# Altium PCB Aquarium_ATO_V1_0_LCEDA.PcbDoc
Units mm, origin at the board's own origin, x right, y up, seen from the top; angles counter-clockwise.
Board outline 120 x 72 mm, 2 copper layers (Top Layer, Bottom Layer), stack 1.58 mm thick; 64 components, 41 nets, 182 pads, 109 vias.
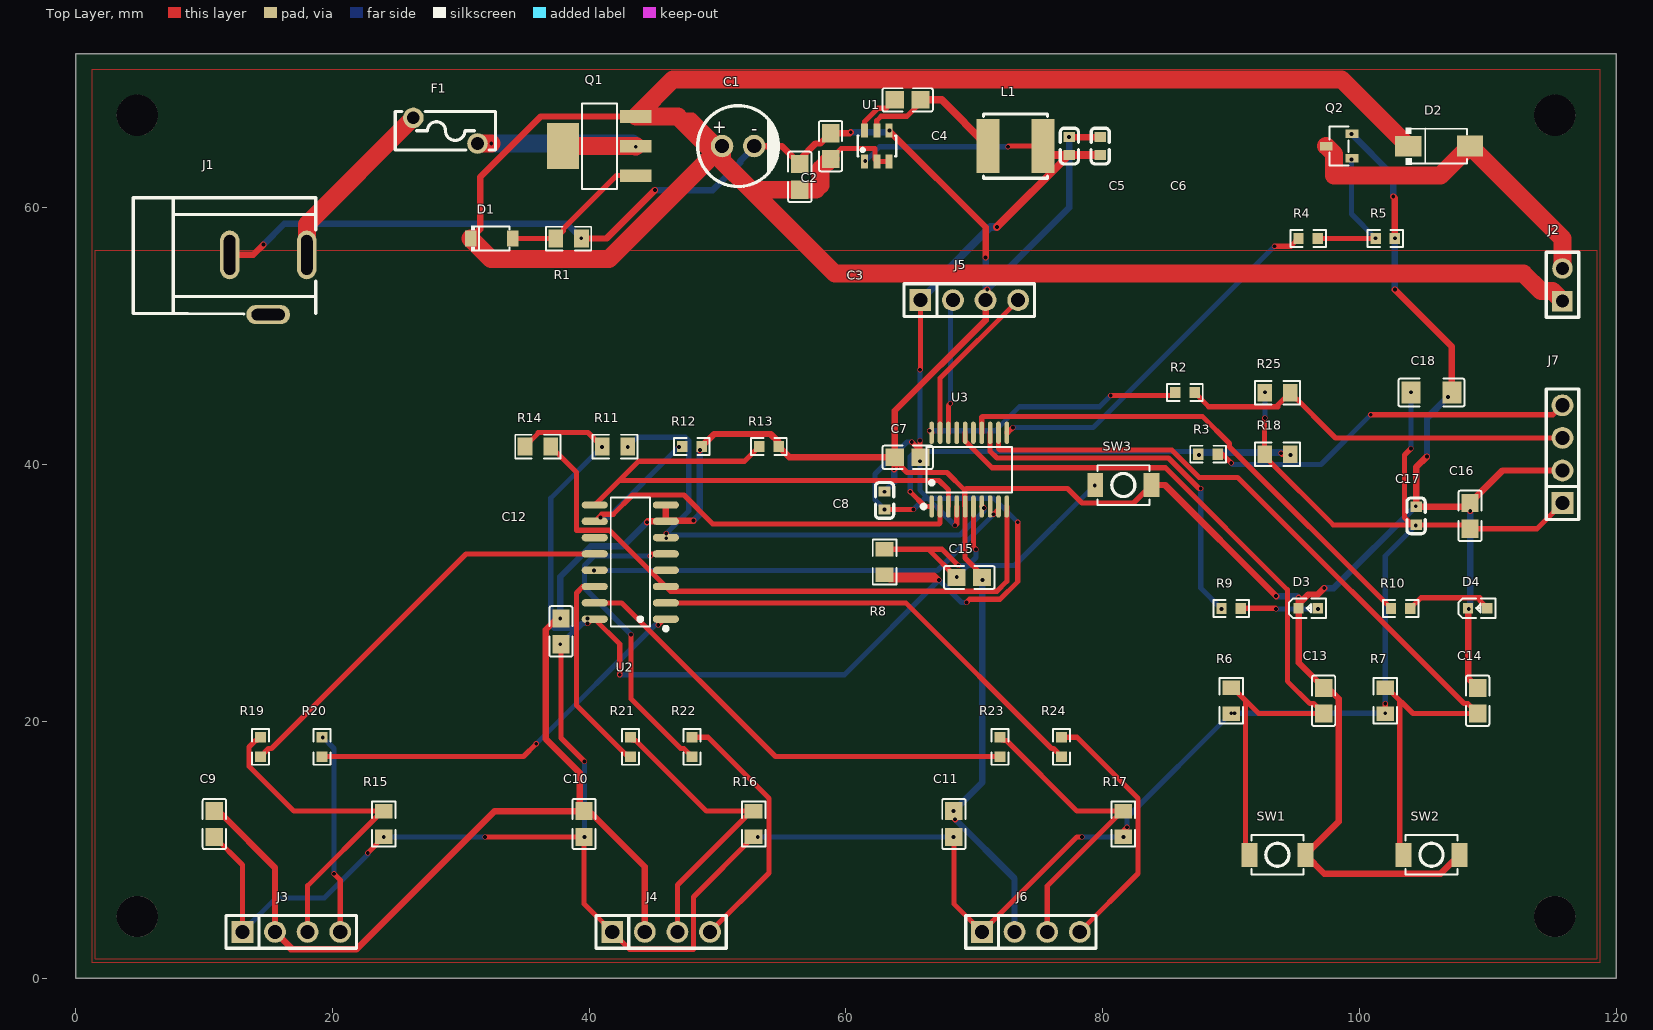
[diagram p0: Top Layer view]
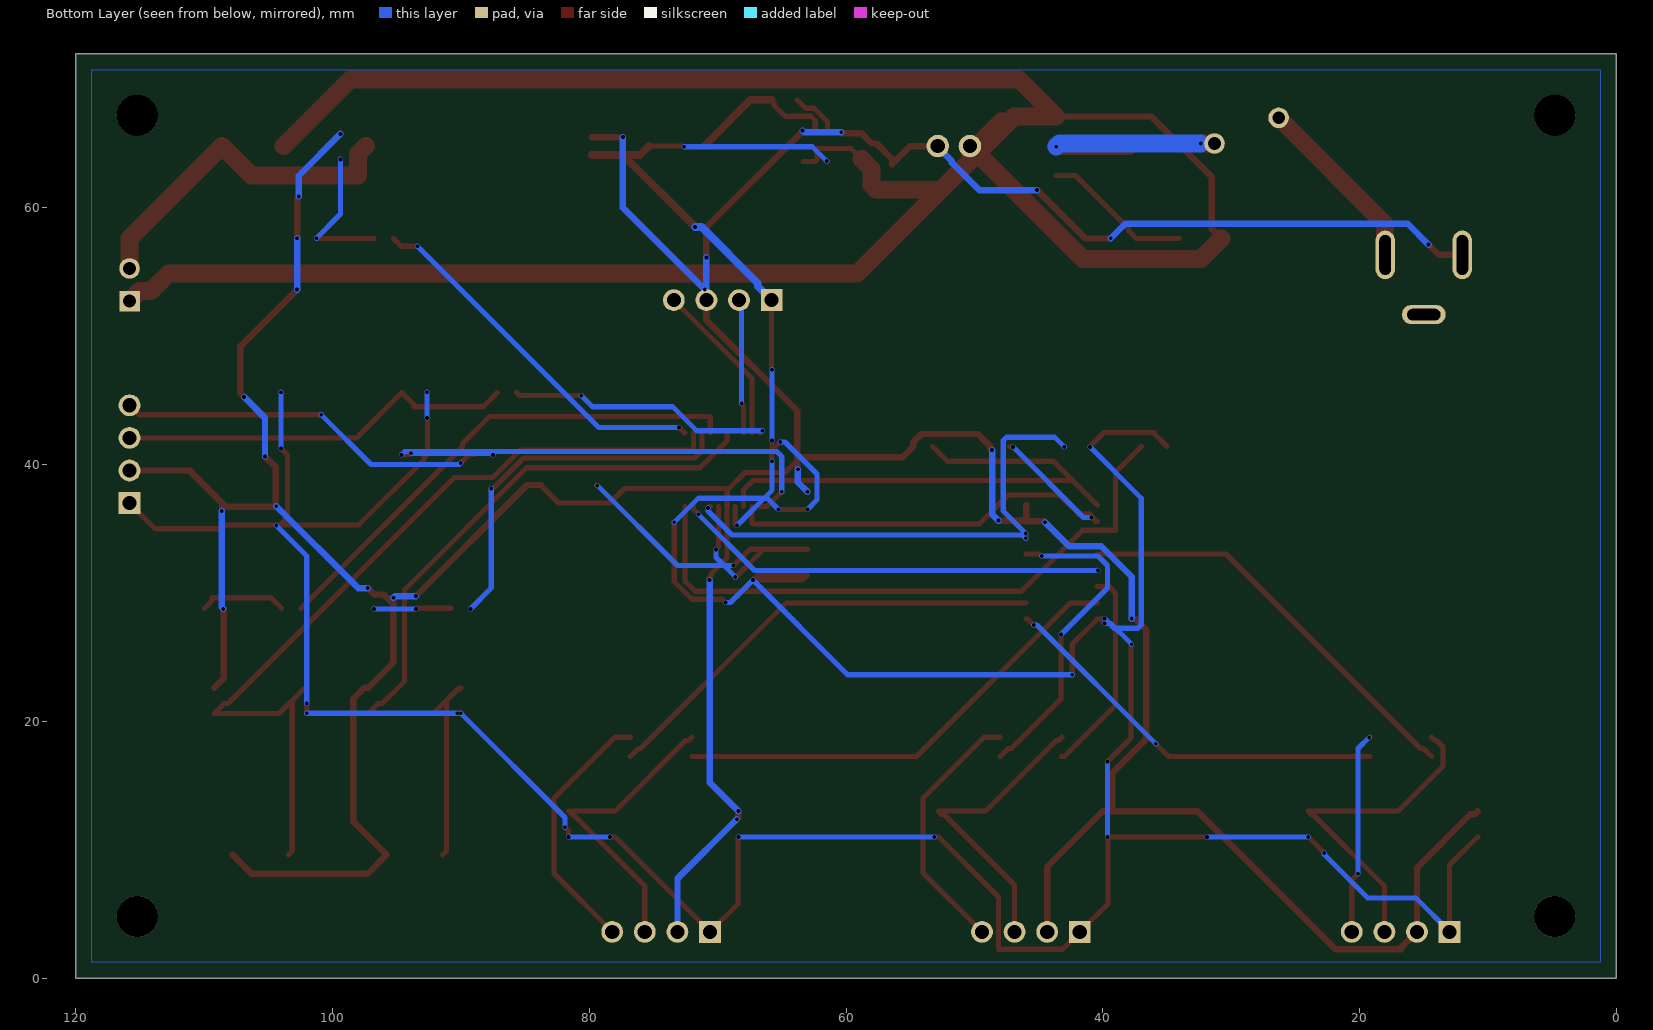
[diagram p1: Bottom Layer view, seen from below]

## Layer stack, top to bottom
Top Solder Mask Layer: solder mask 0.0102, Dk 3.3
Top Layer: signal copper 0.0356
Dielectric1: surface 1.5088, FR4, Dk 4.5
Bottom Layer: signal copper 0.0356
Bottom Solder Mask Layer: solder mask 0.0102, Dk 3.3

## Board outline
0,0 120,0 120,72 0,72

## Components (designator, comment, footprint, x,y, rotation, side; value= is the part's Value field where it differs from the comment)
C1 "47uF" CAP-TH_BD6.3-P2.50-D0.6-FD 51.6,64.8 r0 top
C2 "10uF" C0805#1 56.4,62.4 r90 top
C3 "100nF" C0805#1 58.8,64.8 r90 top
C4 "100nF" C0805#2 64.8,68.4 r0 top
C5 "22uF" C0603#1 77.4,64.8 r90 top
C6 "22uF" C0603#1 79.8,64.8 r90 top
C7 "100nF" C0805#2 64.8,40.56 r180 top
C8 "4.7uF" C0603#2 63,37.2 r90 top
C9 "100nF" C0805#2 10.8,12 r90 top
C10 "100nF" C0805#3 39.6,12 r90 top
C11 "100nF" C0805#2 68.4,12 r90 top
C12 "100nF" C0805#2 37.8,27 r90 top
C13 "100nF" C0805#2 97.2,21.6 r90 top
C14 "100nF" C0805#2 109.2,21.6 r90 top
C15 "100nF" C0805#3 69.6,31.2 r0 top
C16 "100nF" C0805#2 108.6,36 r90 top
C17 "10uF" C0603#2 104.4,36 r90 top
C18 "220uF" C1206 105.6,45.6 r0 top
D1 "BZT52C10" SOD-123_L2.7-W1.6-LS3.7-RD 32.4,57.6 r0 top
D2 "SS16" SMA_L4.3-W2.6-LS5.0-RD 106.2,64.8 r0 top
D3 "FC-1608G1-520" LED0603-RD 96,28.8 r0 top
D4 "XL-1608SURC-06" LED0603-RD_RED 109.2,28.8 r0 top
F1 "RL60-050" FUSE-TH_L7.8-W3.0-P5.10-D0.5-S2.00 28.8,66 r0 top
J1 "DC005-T25" DC-IN-TH_DC-005-20A-1 15,54 r0 top
J2 "LAIL-PZ2.54-2P-L" CONN-TH_LAIL-PZ2.54-2P-L 115.8,54 r90 top
J3 "HX PZ2.54-1x4P ZZ" HDR-TH_4P-P2.54-V-M 16.8,3.6 r0 top
J4 "HX PZ2.54-1x4P ZZ" HDR-TH_4P-P2.54-V-M 45.6,3.6 r0 top
J5 "HX PZ2.54-1x4P ZZ" HDR-TH_4P-P2.54-V-M 69.6,52.8 r0 top
J6 "HX PZ2.54-1x4P ZZ" HDR-TH_4P-P2.54-V-M 74.4,3.6 r0 top
J7 "HX PZ2.54-1x4P ZZ" HDR-TH_4P-P2.54-V-M 115.8,40.8 r90 top
L1 "3.9uH" IND-SMD_L5.0-W5.0_FNR50XXS 73.2,64.8 r0 top
Q1 "DMP6023LE-13" SOT-223-4_L6.5-W3.5-P2.30-LS7.0-BR 40.8,64.8 r0 top
Q2 "AO3400A" SOT-23-3_L2.9-W1.3-P1.90-LS2.4-BR 98.4,64.8 r0 top
R1 "47kΩ" R0805 38.4,57.6 r0 top
R2 "1kΩ" R0603#1 86.4,45.6 r0 top
R3 "1kΩ" R0603#2 88.2,40.8 r0 top
R4 "1kΩ" R0603#1 96,57.6 r0 top
R5 "100kΩ" R0603#2 102,57.6 r0 top
R6 "10kΩ" R0805 90,21.6 r90 top
R7 "10kΩ" R0805 102,21.6 r90 top
R8 "10kΩ" R0805 63,32.4 r90 top
R9 "1kΩ" R0603#2 90,28.8 r0 top
R10 "1kΩ" R0603#1 103.2,28.8 r0 top
R11 "10kΩ" R0805 42,41.4 r0 top
R12 "100kΩ" R0603#2 48,41.4 r0 top
R13 "100kΩ" R0603#1 54,41.4 r0 top
R14 "10kΩ" R0805 36,41.4 r0 top
R15 "10kΩ" R0805 24,12 r90 top
R16 "10kΩ" R0805 52.8,12 r90 top
R17 "10kΩ" R0805 81.6,12 r90 top
R18 "10kΩ" R0805 93.6,40.8 r0 top
R19 "1kΩ" R0603#1 14.4,18 r90 top
R20 "1kΩ" R0603#3 19.2,18 r90 top
R21 "1kΩ" R0603#1 43.2,18 r90 top
R22 "1kΩ" R0603#1 48,18 r90 top
R23 "1kΩ" R0603#3 72,18 r90 top
R24 "1kΩ" R0603#1 76.8,18 r90 top
R25 "10kΩ" R0805 93.6,45.6 r0 top
SW1 "TS-1088-AR02016" SW-SMD_L3.9-W3.0-P4.45 93.6,9.6 r0 top
SW2 "TS-1088-AR02016" SW-SMD_L3.9-W3.0-P4.45 105.6,9.6 r0 top
SW3 "TS-1088-AR02016" SW-SMD_L3.9-W3.0-P4.45 81.6,38.4 r0 top
U1 "AP63203WU-7" TSOT-26_L2.9-W1.6-P0.95-LS2.8-BL 62.4,64.8 r0 top
U2 "74HC4052D,652" SO-16_L9.9-W3.9-P1.27-LS6.0-BL 43.2,32.4 r90 top
U3 "STM32G030F6P6" TSSOP-20_L6.5-W4.4-P0.65-LS6.4-BL 69.6,39.6 r0 top

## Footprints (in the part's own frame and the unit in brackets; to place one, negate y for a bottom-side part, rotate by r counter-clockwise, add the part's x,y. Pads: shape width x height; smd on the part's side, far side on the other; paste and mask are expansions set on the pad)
C0603#1 [mil]
  rect 31.5x35.4 smd: 1(-27.6,0) 2(27.6,0)
  silkscreen extent -55,-28 55,28
C0603#2 [mil]
  rect 31.5x35.4 smd: 1(-27.5,0) 2(27.6,0)
  silkscreen extent -55,-28 55,28
C0805#1 [mil]
  rect 55.5x53.1 smd paste-3937 mask+2: 1(-39.4,0) 2(39.3,0)
  silkscreen extent -77,-36 77,36
C0805#2 [mil]
  rect 55.5x53.1 smd paste-3937 mask+2: 1(-39.4,0) 2(39.4,0)
  silkscreen extent -77,-36 77,36
C0805#3 [mil]
  rect 55.5x53.1 smd paste-3937 mask+2: 1(-39.3,0) 2(39.4,0)
  silkscreen extent -77,-36 77,36
C1206 [mil]
  rect 58.5x68 smd paste-3937 mask+2: 1(-62.7,0) 2(62.7,0)
  silkscreen extent -101,-43 101,43
CAP-TH_BD6.3-P2.50-D0.6-FD [mm]
  round 1.75 hole 1.1 paste+0 mask+0.051: 1(-1.25,0) 2(1.25,0)
  silkscreen extent -3.15,-3.15 3.21,3.15
CONN-TH_LAIL-PZ2.54-2P-L [mil]
  rect 63x63 hole 39.4 paste+0 mask+2: 1(-50,0)
  round 63 hole 39.4 paste+0 mask+2: 2(50,0)
  silkscreen extent -100,-50 100,50
DC-IN-TH_DC-005-20A-1 [mil]
  oval 59.1x149.6 hole 35.4 slot 122.1 at 90 deg: 1(118.2,91.5) 2(-118.1,91.5)
  oval 133.9x59.1 hole 35.4 slot 102.4 at 0 deg: 3(0,-91.5)
  silkscreen extent -414,-90 146,267
FUSE-TH_L7.8-W3.0-P5.10-D0.5-S2.00 [mil]
  round 63 hole 39.4: 1(-98.4,39.4) 2(98.4,-39.4)
  silkscreen extent -154,-59 154,59
HDR-TH_4P-P2.54-V-M [mm]
  rect 1.699x1.699 hole 1.1: 1(-3.81,0)
  round 1.699 hole 1.1: 2(-1.27,0) 3(1.27,0) 4(3.81,0)
  silkscreen extent -5.08,-1.27 5.08,1.27
IND-SMD_L5.0-W5.0_FNR50XXS [mm]
  rect 1.801x4.201 smd: 1(-2.149,0) 2(2.149,0)
  silkscreen extent -2.5,-2.5 2.5,2.5
LED0603-RD [mil]
  rect 31.5x31.5 smd: 1(-29.5,0) 2(29.5,0)
  silkscreen extent -59,-29 55,30
LED0603-RD_RED [mil]
  rect 31.5x31.5 smd: 1(-29.5,-0.1) 2(29.5,0.2)
  silkscreen extent -59,-29 55,30
R0603#1 [mil]
  rect 31.8x34 smd paste-3937 mask+2: 1(-29.7,0) 2(29.7,0)
  silkscreen extent -54,-26 54,26
R0603#2 [mil]
  rect 31.8x34 smd paste-3937 mask+2: 1(-29.7,0) 2(29.6,0)
  silkscreen extent -55,-26 54,26
R0603#3 [mil]
  rect 31.8x34 smd paste-3937 mask+2: 1(-29.6,0) 2(29.7,0)
  silkscreen extent -54,-26 54,26
R0805 [mm]
  rect 1.133x1.377 smd paste-100 mask+0.051: 1(-1.001,0) 2(1.001,0)
  silkscreen extent -1.76,-0.92 1.76,0.92
SMA_L4.3-W2.6-LS5.0-RD [mm]
  rect 2.047x1.621 smd: 1(-2.403,-0.01) 2(2.403,0.01)
  silkscreen extent -2.61,-1.44 2.16,1.44
SO-16_L9.9-W3.9-P1.27-LS6.0-BL [mil]
  oval 22.6x80.2 smd: 1(-175,-109) 2(-125,-109) 3(-75,-109) 4(-25,-109) 5(25,-109) 6(75,-109) 7(125,-109) 8(175,-109) 9(175,109) 10(125,109) 11(75,109) 12(25,109) 13(-25,109) 14(-75,109) 15(-125,109) 16(-175,109)
  silkscreen extent -210,-115 198,60
SOD-123_L2.7-W1.6-LS3.7-RD [mil]
  rect 35.8x48 smd: 1(-64.4,0) 2(64.4,0)
  silkscreen extent -63,-40 54,40
SOT-23-3_L2.9-W1.3-P1.90-LS2.4-BR [mm]
  rect 1.001x0.65 smd: 1(1.001,-0.95) 2(1.001,0.95) 3(-1.001,0)
  silkscreen extent -0.73,-1.53 0.73,1.53
SOT-223-4_L6.5-W3.5-P2.30-LS7.0-BR [mm]
  rect 2.469x0.98 smd: 1(2.835,-2.301) 2(2.835,0) 3(2.835,2.301)
  rect 2.469x3.599 smd: 4(-2.835,0)
  silkscreen extent -1.37,-3.33 1.37,3.33
SW-SMD_L3.9-W3.0-P4.45 [mil]
  rect 48.4x73.2 smd: 1(-86,0) 2(86,0)
  silkscreen extent -80,-61 80,61
TSOT-26_L2.9-W1.6-P0.95-LS2.8-BL [mm]
  rect 0.551x1.1 smd paste+0 mask+0.051: 1(-0.95,-1.199) 2(0,-1.199) 3(0.95,-1.199) 4(0.95,1.199) 5(0,1.199) 6(-0.95,1.199)
  silkscreen extent -1.5,-0.8 1.5,0.8
TSSOP-20_L6.5-W4.4-P0.65-LS6.4-BL [mil]
  oval 14.3x68.6 smd: 1(-115.2,-113) 2(-89.6,-113) 3(-64,-113) 4(-38.4,-113) 5(-12.8,-113) 6(12.8,-113) 7(38.4,-113) 8(64,-113) 9(89.6,-113) 10(115.2,-113) 11(115.2,113) 12(89.6,113) 13(64,113) 14(38.4,113) 15(12.8,113) 16(-12.8,113) 17(-38.4,113) 18(-64,113) 19(-89.6,113) 20(-115.2,113)
  silkscreen extent -146,-119 131,70

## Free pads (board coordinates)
  round 3.2 hole 3.2 unplated paste+0 mask+0: MH1(4.8,67.2) MH2(115.2,67.2) MH3(4.8,4.8) MH4(115.2,4.8)

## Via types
v1: diameter 0, hole 0.3, Top Layer to Bottom Layer, 109 vias

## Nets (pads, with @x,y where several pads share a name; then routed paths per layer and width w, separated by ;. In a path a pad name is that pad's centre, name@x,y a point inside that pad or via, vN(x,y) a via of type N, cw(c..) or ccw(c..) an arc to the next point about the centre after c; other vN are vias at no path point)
+3V3: C5.1 C6.1 C7.1 C8.1 C9.1 C10.1 C11.1 C12.1 C16.1 C17.1 C18.1 J3.1 J4.1 J5.1 J6.1 J7.1 L1.2 R6.1 R7.1 R8.1 R11.1 R14.1 R15.1 R16.1 R17.1 R18.1 R25.1 U1.1 U2.16 U3.4 | length 361
  Top Layer w0.4: C9.1 12.99,8.809 J3.1 v1(13,3.625) ; v1(22.75,9.75) R15.1 ; v1(31.875,11) C10.1 ; R14.1 36,42.401 36,42.5 39.899,42.5 R11.1 v1(41,41.375) ; v1(37.75,26) C12.1 37.8,18.7 v1(39.625,16.875) ; v1(39.625,11) C10.1 ; v1(39.875,27.625) 40.205,27.955 U2.16 ; v1(39.875,28) 39.92,27.955 U2.16 ; v1(42.375,23.625) 42.375,26.011 U2.16 ; v1(53.125,11) R16.1 48.125,6.324 48.125,2.25 43.14,2.25 J4.1 39.6,5.79 C10.1 ; U1.1 61.474,63.625 v1(61.5,63.625) ; v1(63,36.5) C8.1 v1(65.25,36.5) ; v1(65.125,41.75) 65.801,41.074 C7.1 ; v1(65.75,40.25) 65.801,40.301 C7.1 ; v1(65.75,41.875) 65.75,40.611 C7.1 ; v1(65.75,47.375) 65.79,47.415 J5.1 ; v1(68.375,11) C11.1 68.4,5.79 J6.1 77.99,11 v1(78.375,11) ; v1(68.5,35.25) 68.625,35.375 U3.4 ; v1(69.375,29.25) 69.625,29.5 72,29.5 73.375,30.875 v1(73.375,35.5) ; v1(72.625,64.75) 72.675,64.8 L1.2 ; v1(81.625,11) R17.1 81.6,11.475 v1(81.875,11.75) ; v1(90,20.625) R6.1 90.224,20.599 v1(90.25,20.625) ; R25.1 v1(92.625,45.625) ; v1(92.625,43.625) 92.599,43.599 R18.1 92.875,40.524 92.875,40.375 97.949,35.301 C17.1 ; v1(102,20.625) R7.1 v1(102,21.375) ; v1(104,41.25) 103.5,40.75 103.5,35.875 104.074,35.301 C17.1 ; v1(104,45.625) C18.1 ; v1(104.375,35.25) 104.375,35.276 C17.1 ; J7.1 113.809,34.999 C16.1 108.298,35.301 C17.1 ; R8.1 66.851,31.399 v1(67.25,31) 63.399,31 R8.1
  Top Layer w0.6: v1(65.75,52.75) J5.1 ; v1(71.75,58.5) 77.349,64.099 C5.1 ; L1.2 76.05,64.099 C5.1 ; C6.1 C5.1
  Bottom Layer w0.4: v1(13,3.625) 15.625,6.25 19.375,6.25 22.75,9.625 v1(22.75,9.75) ; v1(24,11) v1(31.875,11) ; v1(37.75,26) 39.375,27.625 v1(39.875,27.625) ; v1(39.625,11) v1(39.625,16.875) ; v1(39.875,28) 39.125,27.25 37.25,27.25 37,27.5 37,37.375 v1(41,41.375) ; v1(42.375,23.625) 59.875,23.625 v1(67.25,31) 69,29.25 v1(69.375,29.25) ; v1(53.125,11) v1(68.375,11) ; v1(61.5,63.625) 62.625,64.75 v1(72.625,64.75) ; v1(63,36.5) 62.25,37.25 62.25,39.25 64.75,41.75 v1(65.125,41.75) ; v1(65.25,36.5) 66.125,37.375 71.5,37.375 v1(73.375,35.5) ; v1(65.75,40.25) 65.75,38 v1(68.5,35.25) ; v1(65.75,41.875) v1(65.75,47.375) ; v1(78.375,11) v1(81.625,11) ; v1(81.875,11.75) 81.875,12.5 v1(90,20.625) ; v1(90.25,20.625) v1(102,20.625) ; v1(92.625,43.625) v1(92.625,45.625) ; v1(102,21.375) 102,32.875 v1(104.375,35.25) ; v1(104,41.25) v1(104,45.625)
  Bottom Layer w0.6: v1(65.75,52.75) 66.875,53.875 66.875,54.125 71.25,58.5 v1(71.75,58.5)
+12V_IN: F1.1 J1.1 | length 14.1
  Top Layer w1.4: J1.1 18.002,58.702 F1.1
AUX_RX: J4.3 R16.2 R21.2 | length 23.9
  Top Layer w0.4: R21.2 43.454,18.5 43.625,18.5 49.124,13.001 R16.2 52.549,12.75 52.375,12.75 46.87,7.245 J4.3
AUX_RX_MUX: R21.1 U2.14 | length 16.2
  Top Layer w0.4: U2.14 39.495,30.495 39,30 39,21.25 43,17.25 R21.1
AUX_TX: J4.4 R22.2 | length 20.3
  Top Layer w0.4: R22.2 49.246,18.754 54,14 54,8.19 J4.4
AUX_TX_MUX: R22.1 U2.5 | length 25.2
  Top Layer w0.4: v1(43.25,26.75) 43.25,21.75 47.125,17.875 47.371,17.875 R22.1 ; v1(44.75,32.875) 44.91,33.035 U2.5
  Bottom Layer w0.4: v1(43.25,26.75) 39.625,30.375 39.625,32.125 40.375,32.875 v1(44.75,32.875)
BST: C4.1 U1.6 | length 3.8
  Top Layer w0.4: U1.6 61.45,66.7 62.5,67.75 63.149,67.75 C4.1
D3_A: D3.2 R9.2 | length 6.1
  Top Layer w0.4: R9.2 93.45,28.8 v1(93.5,28.75) ; v1(96.75,28.75) D3.2
  Bottom Layer w0.4: v1(93.5,28.75) v1(96.75,28.75)
D4_A: D4.2 R10.2 | length 6.8
  Top Layer w0.4: R10.2 104.779,29.625 109.375,29.625 109.375,29.379 D4.2
GND: C1.2 C2.2 C3.2 C5.2 C6.2 C7.2 C8.2 C9.2 C10.2 C11.2 C12.2 C13.2 C14.2 C15.2 C16.2 C17.2 C18.2 D3.1 D4.1 J1.2 J3.2 J4.2 J5.3 J6.2 J7.2 Q2.2 R1.2 R5.2 R12.2 R13.2 SW1.2 SW2.2 SW3.2 U1.4 U2.7 U2.8 U3.5 | length 404.7
  Top Layer w0.4: C7.2 63.799,40.326 64.75,39.375 67.875,39.375 69.25,38 69.25,36.755 U3.5 ; C15.2 70.5,31.301 70.5,31.5 69.275,32.725 U3.5 ; SW3.2 82.384,37 78.375,37 77.25,38.125 69.375,38.125 69.275,38.025 U3.5
  Top Layer w0.5: C9.2 11.051,12.75 11.375,12.75 15.53,8.595 J3.2 16.75,2.38 16.75,2.25 21.875,2.25 32.626,13.001 C10.2 ; J1.2 13.824,56.324 v1(14.625,57.125) ; v1(37.75,28) C12.2 37.501,28.001 36.625,27.125 36.625,18.625 39.25,16 39.25,13.351 C10.2 ; v1(39.375,57.625) R1.2 41.35,57.6 v1(45.125,61.375) ; J4.2 44.33,8.67 39.999,13.001 C10.2 ; v1(44.5,35.5) 44.575,35.575 U2.7 ; U2.8 U2.7 ; v1(48.125,35.625) 46.019,35.625 U2.7 ; v1(48.625,41.125) 48.752,41.252 R12.2 49.727,42.375 54.125,42.375 54.754,41.746 R13.2 55.594,40.56 C7.2 ; v1(52.875,64.75) 52.875,64.775 C1.2 54.998,64.8 C2.2 56.4,63.775 57.625,65 58.002,65 C3.2 60.298,65.798 v1(60.375,65.875) ; v1(63,37.875) C8.2 ; v1(63.375,66) U1.4 70.875,58.474 v1(70.875,56.125) ; v1(63.75,39.625) 63.799,39.674 C7.2 ; v1(68.375,13) C11.2 68.4,12.475 v1(68.5,12.375) ; C15.2 70.601,31.024 v1(70.625,31) ; v1(70.875,52.75) J5.3 ; v1(71,53.625) 70.87,53.495 J5.3 ; v1(73.125,3.625) J6.2 ; v1(77.375,65.5) C5.2 C6.2 ; SW3.2 84.85,38.4 v1(93.5,29.75) ; v1(95.25,29.625) D3.1 ; v1(97.25,30.375) 96.75,29.875 96,29.875 95.251,29.126 D3.1 ; v1(99.375,65.75) Q2.2 ; v1(102.625,60.875) 102.752,60.748 R5.2 v1(102.75,57.625) ; v1(102.75,53.625) 107.193,49.182 C18.2 106.875,45.282 v1(106.875,45.25) ; v1(104.375,36.75) 104.375,36.726 C17.2 ; v1(105.25,40.625) 104.4,39.775 C17.2 ; SW2.2 106.309,8.125 97.259,8.125 SW1.2 98.375,12.191 98.375,21.75 97.524,22.601 C13.2 95.251,24.55 D3.1 ; v1(108.5,28.75) D4.1 108.451,23.35 C14.2 ; v1(108.625,36.375) 108.6,36.4 C16.2 ; J7.2 111.129,39.53 C16.2 ; C7.2 63.799,44.174 70.87,51.245 J5.3 ; C17.2 108.3,36.701 C16.2
  Bottom Layer w0.5: v1(14.625,57.125) 16.25,58.75 38.25,58.75 v1(39.375,57.625) ; v1(37.75,28) 37.75,31.25 40.125,33.625 42.625,33.625 v1(44.5,35.5) ; v1(45.125,61.375) 49.625,61.375 51.75,63.5 51.75,63.625 v1(52.875,64.75) ; v1(48.125,35.625) 48.625,36.125 v1(48.625,41.125) ; v1(60.375,65.875) 63.25,65.875 v1(63.375,66) ; v1(63,37.875) 63.75,38.625 v1(63.75,39.625) ; v1(68.375,13) 70.625,15.25 v1(70.625,31) ; v1(68.5,12.375) 73.125,7.75 v1(73.125,3.625) ; v1(70.875,52.75) v1(70.875,56.125) ; v1(71,53.625) 77.375,60 v1(77.375,65.5) ; v1(93.5,29.75) 95.125,29.75 v1(95.25,29.625) ; v1(97.25,30.375) 98,30.375 v1(104.375,36.75) ; v1(99.375,65.75) 102.625,62.5 v1(102.625,60.875) ; v1(102.75,53.625) v1(102.75,57.625) ; v1(105.25,40.625) 105.25,43.625 v1(106.875,45.25) ; v1(108.5,28.75) 108.625,28.875 v1(108.625,36.375)
KEY_AUTO: C13.1 R6.2 SW1.1 U3.16 | length 63.2
  Top Layer w0.4: U3.16 69.275,41.85 71.375,39.75 84.875,39.75 94.375,30.25 94.375,23.125 96.125,21.375 96.424,21.375 C13.1 92.151,20.599 90.25,22.5 90.101,22.5 R6.2 90.149,22.601 91.125,21.625 91.125,9.891 SW1.1
KEY_MANUAL: C14.1 R7.2 SW2.1 U3.12 | length 68.8
  Top Layer w0.4: U3.12 71.876,41.249 72,41.125 85.375,41.125 87.5,39 90.5,39 108.125,21.375 108.424,21.375 C14.1 104.151,20.599 102.25,22.5 102.101,22.5 R7.2 102.149,22.601 103.125,21.625 103.125,9.891 SW2.1
LED_FAULT: R10.1 U3.14 | length 39.5
  Top Layer w0.4: U3.14 70.575,43.7 70.625,43.75 87.75,43.75 89.875,41.625 89.875,41.371 R10.1
LED_STATUS: R9.1 U3.13 | length 29.1
  Top Layer w0.4: U3.13 71.226,41.024 71.75,40.5 85.125,40.5 87.5,38.125 v1(87.625,38.125) ; R9.1 v1(89.25,28.75)
  Bottom Layer w0.4: v1(87.625,38.125) 87.625,30.375 v1(89.25,28.75)
MAIN_RX: J3.3 R15.2 R19.2 | length 26.6
  Top Layer w0.4: R19.2 14.146,18.5 14,18.5 13.5,18 13.5,16.5 16.999,13.001 R15.2 23.749,12.75 23.625,12.75 18.07,7.195 J3.3
MAIN_RX_MUX: R19.1 U2.12 | length 32.6
  Top Layer w0.4: R19.1 15.029,17.875 15.25,17.875 30.41,33.035 U2.12
MAIN_TX: J3.4 R20.2 | length 15.8
  Top Layer w0.4: R20.2 v1(19.25,18.75) ; v1(20.125,8.125) 20.61,7.64 J3.4
  Bottom Layer w0.4: v1(19.25,18.75) 20.125,17.875 v1(20.125,8.125)
MAIN_TX_MUX: R20.1 U2.1 | length 31.2
  Top Layer w0.4: R20.1 34.873,17.248 v1(35.875,18.25) ; v1(45.375,27.5) 45.83,27.955 U2.1
  Bottom Layer w0.4: v1(35.875,18.25) 45.125,27.5 v1(45.375,27.5)
MUX_E: R11.2 U2.6 U3.7 | length 39.7
  Top Layer w0.4: v1(43,41.375) R11.2 ; v1(46,34.25) 46,34.274 U2.6 45.969,34.594 v1(46,34.625) ; U3.7 70.645,36.73 v1(70.75,36.625)
  Bottom Layer w0.4: v1(43,41.375) 43.75,42.125 47.5,42.125 47.75,41.875 47.75,36.375 v1(46,34.625) ; v1(46,34.25) 46.25,34.5 68.875,34.5 70.75,36.375 v1(70.75,36.625)
MUX_S0: R12.1 U2.10 U3.2 | length 39.2
  Top Layer w0.4: v1(40.875,35.875) 40.575,35.575 U2.10 40.981,36.125 41.875,36.125 43.375,37.625 47.375,37.625 49.625,35.375 67.25,35.375 67.324,35.449 U3.2 ; v1(47,41.375) 47.221,41.375 R12.1
  Bottom Layer w0.4: v1(40.875,35.875) 41.5,35.875 v1(47,41.375)
MUX_S1: R13.1 U2.9 U3.3 | length 44.6
  Top Layer w0.4: R13.1 52.096,40.25 43.836,40.25 U2.9 42.336,38.75 67.25,38.75 67.974,38.026 U3.3
NRST: C15.1 R8.2 SW3.1 U3.6 | length 32.3
  Top Layer w0.4: v1(68.625,31.25) 68.625,31.223 C15.1 66.401,33.401 R8.2 67.474,33.401 v1(68.75,32.125) ; U3.6 69.925,33.575 v1(70.125,33.375) ; v1(79.375,38.375) 79.391,38.375 SW3.1
  Bottom Layer w0.4: v1(68.625,31.25) 70.125,32.75 v1(70.125,33.375) ; v1(68.75,32.125) 73.125,32.125 v1(79.375,38.375)
PUMP_CMD: R4.1 U3.11 | length 29
  Top Layer w0.4: U3.11 72.595,42.47 v1(73,42.875) ; v1(93.375,57) 94.646,57 R4.1
  Bottom Layer w0.4: v1(73,42.875) 79.25,42.875 v1(93.375,57)
PUMP_GATE: Q2.1 R4.2 R5.1 | length 11.5
  Top Layer w0.4: R4.2 R5.1 v1(101.25,57.625) ; v1(99.375,63.75) 99.401,63.776 Q2.1
  Bottom Layer w0.4: v1(99.375,63.75) 99.375,59.5 v1(101.25,57.625)
PUMP_NEG: D2.2 J2.2 Q2.3 | length 26.6
  Top Layer w1.4: Q2.3 98,64.199 98,62.5 106.293,62.5 D2.2 115.8,57.613 J2.2
Q1_GATE: D1.2 Q1.1 R1.1 | length 11.7
  Top Layer w0.4: D1.2 R1.1 38,58.201 38,58.375 42.124,62.499 Q1.1
RES_RX: J6.3 R17.2 R23.2 | length 23.9
  Top Layer w0.4: R23.2 72.254,18.5 72.5,18.5 77.999,13.001 R17.2 81.349,12.75 81.25,12.75 75.67,7.17 J6.3
RES_RX_MUX: R23.1 U2.15 | length 36.5
  Top Layer w0.4: U2.15 42.525,29.225 54.502,17.248 R23.1
RES_TX: J6.4 R24.2 | length 20.2
  Top Layer w0.4: R24.2 77.996,18.754 82.75,14 82.75,8.14 J6.4
RES_TX_MUX: R24.1 U2.2 | length 35.8
  Top Layer w0.4: U2.2 64.65,29.225 76,17.875 76.171,17.875 R24.1
SENS_RX: R14.2 U2.3 U3.10 | length 49
  Top Layer w0.4: R14.2 39,39.401 39,34.875 41.589,34.875 U2.3 46.339,30.125 71.75,30.125 72.526,30.901 U3.10
SENS_TX: U2.13 U3.9 | length 33.8
  Top Layer w0.4: v1(40.375,31.75) 40.416,31.75 U2.13 ; v1(71.5,36.125) 71.876,36.501 U3.9
  Bottom Layer w0.4: v1(40.375,31.75) 67.125,31.75 v1(71.5,36.125)
SW: C4.2 L1.1 U1.5 | length 11.7
  Top Layer w0.4: U1.5 62.4,66.775 62.75,67.125 64.75,67.125 65.625,68 65.625,68.224 C4.2
  Top Layer w0.6: C4.2 67.451,68.4 L1.1
SWCLK: J5.4 U3.19 | length 12.9
  Top Layer w0.4: U3.19 67.324,46.714 J5.4
SWDIO: J5.2 U3.18 | length 10.5
  Top Layer w0.4: U3.18 67.974,44.599 v1(68.125,44.75) ; J5.2 v1(68.375,52.75)
  Bottom Layer w0.4: v1(68.125,44.75) 68.125,52.5 v1(68.375,52.75)
VIN_FUSED: F1.2 Q1.2 Q1.4 | length 18.1
  Top Layer w1.4: F1.2 v1(32.375,65) ; Q1.4 Q1.2 v1(43.625,64.75)
  Bottom Layer w1.4: v1(32.375,65) 43.375,65 v1(43.625,64.75)
VIN_P: C1.1 C2.1 C3.1 D1.1 D2.1 J2.1 Q1.3 U1.2 U1.3 | length 210.5
  Top Layer w0.4: C3.1 59.626,64.625 62.25,64.625 62.25,63.751 U1.2 U1.3
  Top Layer w0.5: D1.1 31.5,58.336 31.5,62.375 36.226,67.101 Q1.3
  Top Layer w0.65: Q1.3 48.049,67.101 C1.1
  Top Layer w1.4: D1.1 32.364,56 41.55,56 C1.1 50.35,63.65 52.601,61.399 C2.1 57.649,61.399 58,61.75 58,62.999 C3.1 ; D2.1 98.587,70 46.533,70 Q1.3 46.899,67.101 59.125,54.875 112.75,54.875 114.125,53.5 115.03,53.5 J2.1
WIFI_MODULE_RX: J7.3 R2.2 R25.2 | length 31.1
  Top Layer w0.4: R2.2 88.254,44.5 93.625,44.5 93.625,44.624 R25.2 98.131,42.07 J7.3
WIFI_MODULE_TX: J7.4 R3.2 | length 29.1
  Top Layer w0.4: R3.2 89.325,40.8 v1(90,40.125) ; v1(100.875,43.875) 115.065,43.875 J7.4
  Bottom Layer w0.4: v1(90,40.125) 90.125,40 97,40 v1(100.875,43.875)
WIFI_RX: R3.1 R18.2 U3.1 | length 42.1
  Top Layer w0.4: v1(65,37.875) 66.145,36.73 U3.1 ; R3.1 v1(87.5,40.75) ; v1(93.875,40.875) 93.95,40.8 R18.2 94.625,40.776 v1(94.625,40.75)
  Bottom Layer w0.4: v1(65,37.875) 65,40.625 65.375,41 94.375,41 v1(94.625,40.75) ; v1(87.5,40.75) 87.625,40.875 v1(93.875,40.875)
WIFI_TX: R2.1 U3.20 | length 20.6
  Top Layer w0.4: v1(66.5,42.625) 66.655,42.47 U3.20 ; v1(80.625,45.375) 85.421,45.375 R2.1
  Bottom Layer w0.4: v1(66.5,42.625) 71.625,42.625 73.5,44.5 79.75,44.5 v1(80.625,45.375)
pads on no net: J1.3 U2.4 U2.11 U3.8 U3.15 U3.17

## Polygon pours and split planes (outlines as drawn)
GND on Top Layer (solid, remove dead copper): 1.25,1.25 118.75,1.25 118.75,70.75 1.25,70.75
GND on Bottom Layer (solid, remove dead copper): 1.25,1.25 118.75,1.25 118.75,70.75 1.25,70.75
+3V3 on Top Layer (solid, remove dead copper): 1.5,1.5 118.5,1.5 118.5,56.64 1.5,56.64

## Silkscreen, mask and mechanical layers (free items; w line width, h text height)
Mechanical Layer:
  the board outline again, w0.2
Inner31:
  text "AQUARIUM ATO V1.0" at 2.4,69.6 h1
  text "POWER / BUCK" at 21.6,69.6 h0.8
  text "PUMP" at 98.4,69.6 h0.8
  text "MCU / SWD" at 61.2,51.6 h0.8
  text "WIFI / USER" at 92.4,33.6 h0.8
  text "SENSORS" at 2.4,24 h0.8
  text "ROUTED - IMPORT / DRC REQUIRED" at 82.8,2.4 h0.7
